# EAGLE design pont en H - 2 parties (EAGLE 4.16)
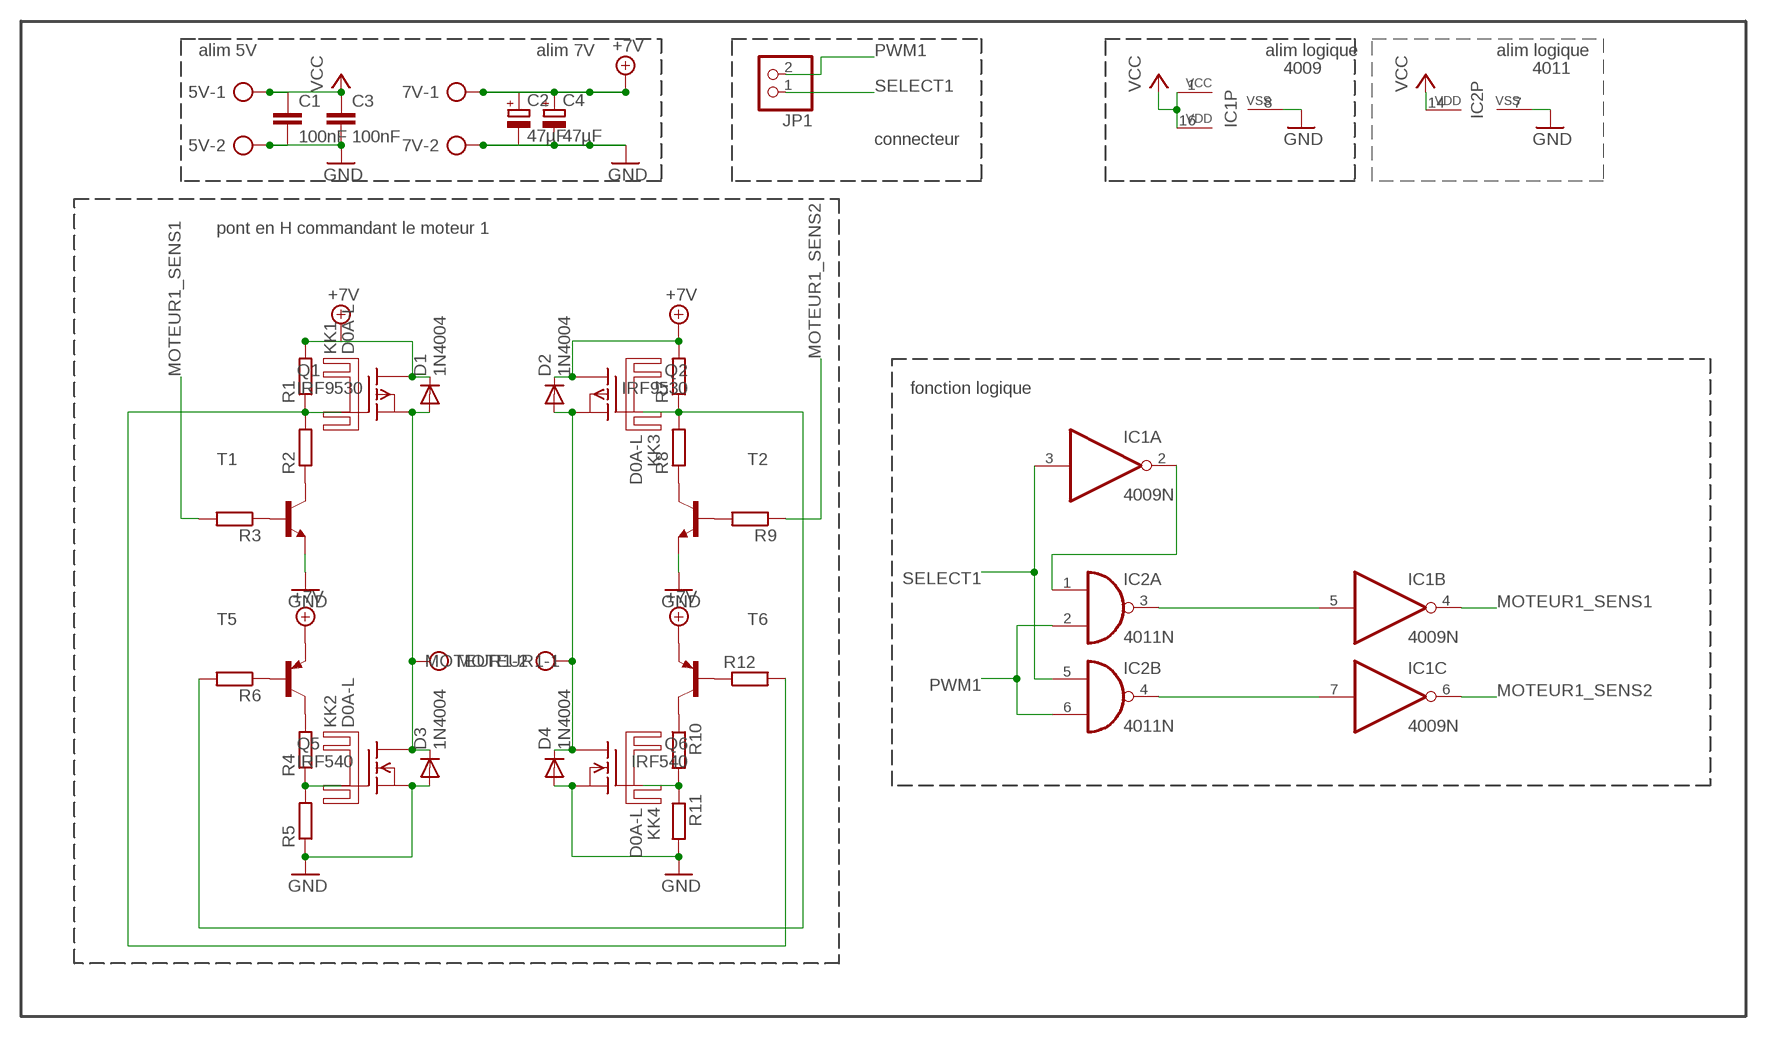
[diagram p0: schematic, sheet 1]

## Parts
5V  AK500/2  [AK500/2]
7V  AK500/2  [AK500/2]
C1  100nF  C-EU025-024X044  [C025-024X044]
C2  47µF  CPOL-EUE2-5  [E2-5]
C3  100nF  C-EU025-024X044  [C025-024X044]
C4  47µF  CPOL-EUE2-5  [E2-5]
D1  1N4004  [DO41-10]
D2  1N4004  [DO41-10]
D3  1N4004  [DO41-10]
D4  1N4004  [DO41-10]
IC1  4009N  [DIL16]
IC2  4011N  [DIL14]
JP1  PINHD-1X2  [1X02]
KK1  D0A-L  [D02A-L]
KK2  D0A-L  [D02A-L]
KK3  D0A-L  [D02A-L]
KK4  D0A-L  [D02A-L]
MOTEUR1  AK500/2  [AK500/2]
Q1  IRF9530  [TO220]
Q2  IRF9530  [TO220]
Q5  IRF540  [TO220]
Q6  IRF540  [TO220]
R1  R-EU_0207/10  [0207/10]
R2  R-EU_0207/10  [0207/10]
R3  R-EU_0207/10  [0207/10]
R4  R-EU_0207/10  [0207/10]
R5  R-EU_0207/10  [0207/10]
R6  R-EU_0207/10  [0207/10]
R7  R-EU_0207/10  [0207/10]
R8  R-EU_0207/10  [0207/10]
R9  R-EU_0207/10  [0207/10]
R10  R-EU_0207/10  [0207/10]
R11  R-EU_0207/10  [0207/10]
R12  R-EU_0207/10  [0207/10]
T1  BC846-NPN-SOT23-BEC  [SOT23-BEC]
T2  BC846-NPN-SOT23-BEC  [SOT23-BEC]
T5  BC858A-PNP-SOT23-BEC  [SOT23-BEC]
T6  BC858A-PNP-SOT23-BEC  [SOT23-BEC]

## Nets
+7V: 7V.1 C2.+ C4.+ D1.C D2.C Q1.2(D) Q2.2(D) R1.2 R7.2 T5.E T6.E
GND: 5V.2 7V.2 C1.2 C2.- C3.2 C4.- D3.A D4.A IC1.8(P:VSS) IC2.7(P:VSS) Q5.3(S) Q6.3(S) R5.1 R11.2 T1.E T2.E
MOTEUR1_SENS1: IC1.4(B:O) R3.2
MOTEUR1_SENS2: IC1.6(C:O) R9.1
N$1: Q1.1(G) R1.1 R2.2 R12.2
N$2: R2.1 T1.C
N$3: R3.1 T1.B
N$4: Q5.1(G) R4.1 R5.2
N$5: R4.2 T5.C
N$6: R6.1 T5.B
N$7: Q2.1(G) R6.2 R7.1 R8.2
N$8: R8.1 T2.C
N$9: R9.2 T2.B
N$10: R10.1 T6.C
N$11: Q6.1(G) R10.2 R11.1
N$12: R12.1 T6.B
N$13: D1.A D3.C MOTEUR1.1 Q1.3(S) Q5.2(D)
N$16: D2.A D4.C MOTEUR1.2 Q2.3(S) Q6.2(D)
N$31: IC1.5(B:I) IC2.3(A:O)
N$32: IC1.7(C:I) IC2.4(B:O)
N$36: IC1.2(A:O) IC2.1(A:I0)
PWM1: IC2.2(A:I1) IC2.6(B:I1) JP1.2
SELECT1: IC1.3(A:I) IC2.5(B:I0) JP1.1
VCC: 5V.1 C1.1 C3.1 IC1.1(P:VCC) IC1.16(P:VDD) IC2.14(P:VDD)
Unconnected: IC1.9(D:I) IC1.10(D:O) IC1.11(E:I) IC1.12(E:O) IC1.14(F:I) IC1.15(F:O) IC2.8(C:I0) IC2.9(C:I1) IC2.10(C:O) IC2.11(D:O) IC2.12(D:I0) IC2.13(D:I1)

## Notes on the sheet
- alim 5V | alim 7V | alim logique | alim logique
- 4009 | 4011
- connecteur
- pont en H commandant le moteur 1
- fonction logique

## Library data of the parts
5V 7V MOTEUR1 = con-ptr500:AK500/2: CONNECTOR
C1 C3 = rcl:C-EU: CAPACITOR, European symbol
C2 C4 = rcl:CPOL-EU: POLARIZED CAPACITOR, European symbol
D1-D4 = diode:1N4004: DIODE
IC1 = 40xx:4009: Hex BUFFER, inverting
IC2 = 40xx:4011: Quad 2-input NAND
JP1 = pinhead:PINHD-1X2: PIN HEADER
KK1-KK4 = heatsink:D0A-L: HEATSINK
Q1 Q2 = transistor-fet:IRF9530: P-Channel Enhancement MOSFET (HEXFET); -100V; -12A; 0,3Ohm
Q5 Q6 = transistor-fet:IRF540: N-Channel Enhancement MOSFET (HEXFET); 100V; 28A; 0,077Ohm
R1-R12 = rcl:R-EU_: RESISTOR, European symbol
T1 T2 = transistor:*-NPN-: NPN Transistror
T5 T6 = transistor:*-PNP-: PNP Transistror

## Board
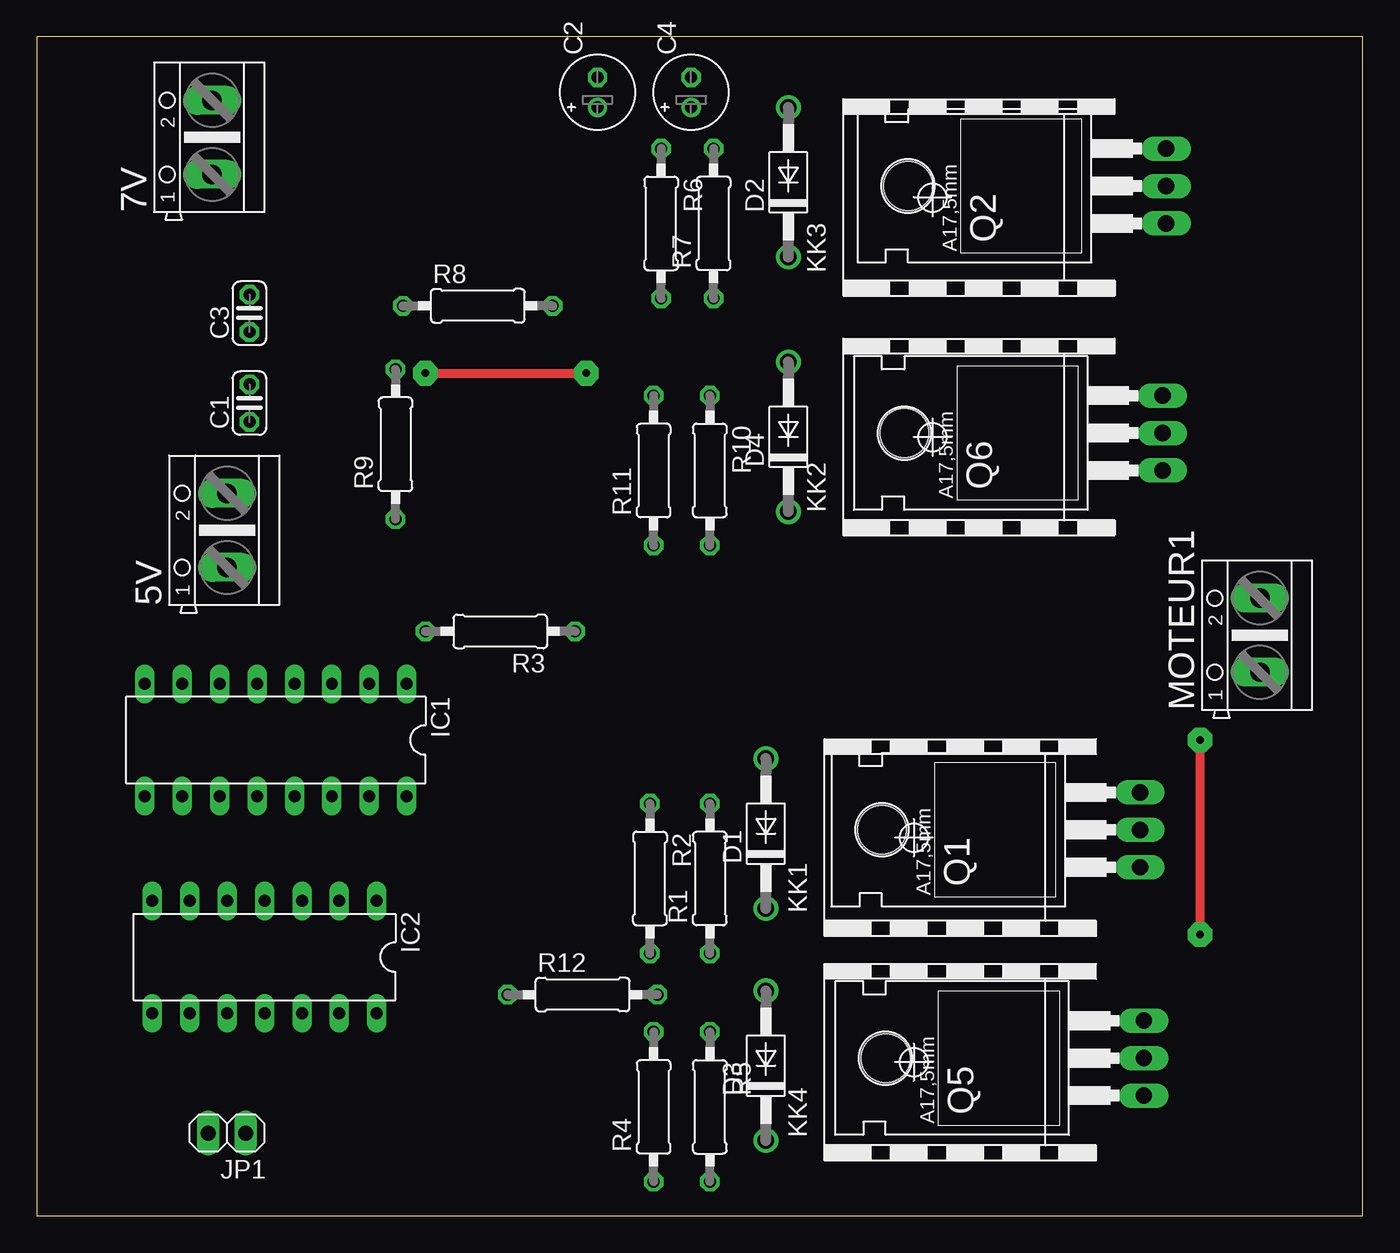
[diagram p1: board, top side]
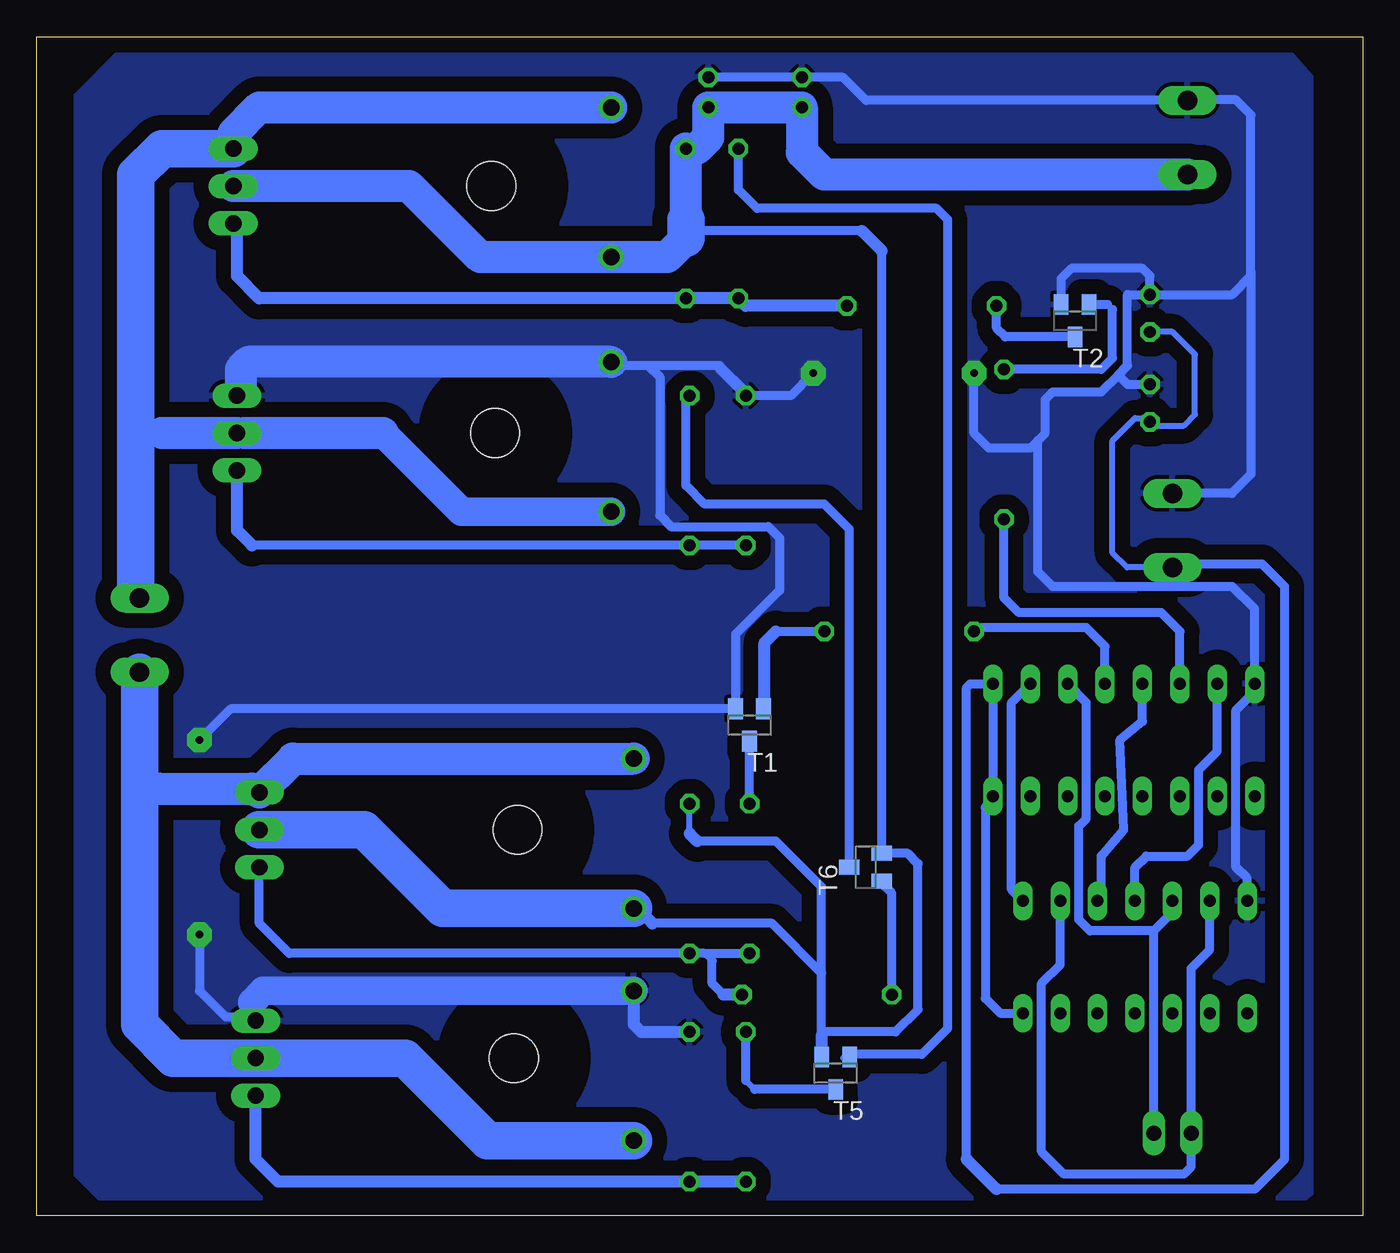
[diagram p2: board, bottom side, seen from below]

Size 90 x 80 mm. Coordinates in mm from the lower left corner, seen from the top.
Outline: 0,0 90,0 90,80 0,80 0,0
Copper layers (1*16): Top 0.035mm / dielectric 1.5mm / Bottom 0.035mm
Design rules "default": minimum track width 10mil, minimum drill 24mil, track to track 8mil, track to pad 8mil, pad to pad 8mil, via to via 8mil, smd to smd 8mil, copper to edge 40mil, drill to drill 8mil, minimum pad ring 10mil, minimum via ring 8mil, stop-mask expansion 4mil, vias tented up to drill 0mil, thermal gap 10mil

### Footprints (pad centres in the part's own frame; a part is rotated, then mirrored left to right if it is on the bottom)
AK500/2 = drill 1.321 long: 1 -2.515,0; 2 2.515,0
C025-024X044 = drill 0.813 octagon: 1 -1.27,0; 2 1.27,0
E2-5 = drill 0.813 pad 1.27 round: + -1.016,0 | drill 0.813 pad 1.27 octagon: - 1.016,0
DO41-10 = drill 1.118 round: A 5.08,0; C -5.08,0
DIL16 = drill 0.813 long: 1 -8.89,-3.81; 2 -6.35,-3.81; 3 -3.81,-3.81; 4 -1.27,-3.81; 5 1.27,-3.81; 6 3.81,-3.81; 7 6.35,-3.81; 8 8.89,-3.81; 9 8.89,3.81; 10 6.35,3.81; 11 3.81,3.81; 12 1.27,3.81; 13 -1.27,3.81; 14 -3.81,3.81; 15 -6.35,3.81; 16 -8.89,3.81
DIL14 = drill 0.813 long: 1 -7.62,-3.81; 2 -5.08,-3.81; 3 -2.54,-3.81; 4 0,-3.81; 5 2.54,-3.81; 6 5.08,-3.81; 7 7.62,-3.81; 8 7.62,3.81; 9 5.08,3.81; 10 2.54,3.81; 11 0,3.81; 12 -2.54,3.81; 13 -5.08,3.81; 14 -7.62,3.81
1X02 = drill 1.016 long: 1 -1.27,0; 2 1.27,0
TO220 = drill 1.118 long: 1 -2.54,-6.35; 2 0,-6.35; 3 2.54,-6.35 | hole 3.302: 0,11.176
0207/10 = drill 0.813 octagon: 1 -5.08,0; 2 5.08,0
SOT23-BEC = smd 1 x 1.4: B -0.95,-1.1; C 0,1.1; E 0.95,-1.1

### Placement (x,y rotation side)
5V  12.92,46.51 90 top
7V  11.9,73.18 90 top
C1  14.44,55.15 90 top
C2  38.06,76.23 90 top
C3  14.44,61.24 90 top
C4  44.41,76.23 90 top
D1  49.49,25.94 90 top
D2  51.02,70.13 90 top
D3  49.49,10.19 90 top
D4  51.02,52.86 90 top
IC1  16.22,32.29 180 top
IC2  15.46,17.55 180 top
JP1  12.92,5.62 180 top
KK1  64.99,25.68 0 top
KK2  66.26,52.86 0 top
KK3  66.26,69.12 0 top
KK4  64.99,10.44 0 top
MOTEUR1  83.02,39.4 90 top
Q1  68.54,26.19 90 top
Q2  70.32,69.88 90 top
Q5  68.8,10.7 90 top
Q6  70.07,53.11 90 top
R1  45.68,22.89 90 top
R2  41.62,22.89 270 top
R3  31.46,39.65 180 top
R4  41.87,7.39 90 top
R5  45.68,7.39 270 top
R6  42.38,67.34 270 top
R7  45.94,67.34 90 top
R8  29.93,61.75 0 top
R9  24.35,52.35 90 top
R10  45.68,50.57 270 top
R11  41.87,50.57 90 top
R12  37.05,15.01 0 top
T1  41.62,33.3 180 bottom
T2  19.52,60.73 180 bottom
T5  35.78,9.68 180 bottom
T6  33.74,23.65 90 bottom

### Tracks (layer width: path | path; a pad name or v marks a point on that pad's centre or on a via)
+7V
  Bottom 0.406: R7.2 46.19,72.42 | 36.73,12.22 36.73,16.47 | 49.24,20.86 D1.C | 45.68,25.94 R1.2
  Bottom 0.61: 36.73,16.47 40.09,19.84 48.22,19.84 | 45.17,25.43 39.84,25.43 36.73,22.31 36.73,12.22 36.79,12.22 36.54,12.47 31.71,12.47 30.19,14 30.19,23.9 30.88,24.6 T6.E 32.64,65.48 | 34,66.83 45.17,66.83 45.94,67.59
  Bottom 0.813: 48.22,19.84 49.24,20.86 | 36.73,12.22 T5.E | 45.17,25.43 45.68,25.94 | 32.64,65.48 34,66.83
  Bottom 2.184: Q2.2 64.73,69.88 59.91,65.05 D2.C 47.21,65.05 45.94,66.32 | 7V.1 36.56,70.66 38.06,72.16 C2.+ C4.+ 44.41,73.18 45.17,72.42 R7.2 45.94,67.59
  Bottom 2.54: D1.C 62.45,20.86 67.78,26.19 Q1.2 | 45.94,67.59 45.94,66.32
GND  (via drill 0.5 pad 1.68)
  Top 0.61: v26.38,57.18 v37.3,57.18 | v78.96,32.29 v78.96,19.08
  Bottom 0.406: C4.- 44.41,77.5 44.16,77.24 | 38.06,76.99 C2.- | D3.A 49.49,15.52 | 51.02,57.69 D4.A | R11.2 41.87,55.91
  Bottom 0.61: 75.4,14.51 75.4,12.98 Q5.3 75.4,13.49 77.18,13.49 78.96,15.27 v78.96,19.08 | 76.16,55.91 Q6.3 | C2.- 44.16,77.24 | 38.06,76.99 37.81,77.24 35.27,77.24 33.72,75.69 7V.2 11.9,75.72 8.6,75.72 7.58,74.7 7.58,64.04 | 41.87,55.91 43.65,57.69 | 48.48,57.69 51.02,57.69 | 14.19,62.51 8.85,62.51 7.58,63.78 7.58,64.04 | T2.E 20.47,63.59 19.77,64.29 14.95,64.29 14.44,63.78 14.44,62.77 14.19,62.51 | 14.19,62.51 C3.2 15.96,62.51 15.96,57.69 16.6,57.05 | IC2.7 7.84,22.89 8.6,23.65 8.6,34.32 7.33,35.59 IC1.8 7.33,41.18 8.85,42.7 21.04,42.7 22.06,43.72 22.06,52.61 21.55,53.11 | 48.48,57.69 47.71,56.92 47.71,47.53 46.95,46.76 40.35,46.76 39.59,46 39.59,42.45 42.57,39.46 T1.E 76.84,34.4 v78.96,32.29 | 43.65,57.69 48.48,57.69 | 43.65,57.69 43.65,57.43 R11.2 38.82,55.65 v37.3,57.18 | v26.38,57.18 26.38,53.11 25.36,52.1 22.57,52.1 21.55,53.11 | 21.55,53.11 21.55,55.4 21.04,55.91 17.74,55.91 16.6,57.05 | C1.2 15.96,56.42 16.6,57.05 | 5V.2 8.88,49.03 7.58,50.32 7.58,64.04
  Bottom 0.813: R5.1 48.98,12.47 49.49,12.98 D3.A
  Bottom 1.93: D3.A 74.64,15.27 75.4,14.51
  Bottom 2.184: D4.A 75.65,57.94 76.16,57.43 76.16,55.91
  pour Bottom (isolate 1.016): 5.3,79.28 84.29,79.02 87.34,75.97 87.34,2.82 85.05,0.54 4.79,0.54 3.52,1.55 3.52,77.24
MOTEUR1_SENS1
  Bottom 0.406: R3.2 26.38,39.4 25.87,39.91
  Bottom 0.61: IC1.4 17.49,38.64 18.76,39.91 25.87,39.91
MOTEUR1_SENS2
  Bottom 0.61: IC1.6 12.41,39.65 13.68,40.92 23.33,40.92 24.35,41.94 R9.1
N$1
  Bottom 0.406: R1.1 44.67,17.81 44.16,17.3
  Bottom 0.61: R2.2 44.67,17.81 72.86,17.81 74.89,19.84 Q1.1 | 43.4,15.01 44.16,15.78 44.16,17.3
  Bottom 0.813: R12.2 43.4,15.01
N$2
  Bottom 0.61: R2.1 T1.C
N$3
  Bottom 0.406: 40.67,34.51 40.6,34.57
  Bottom 0.61: 39.84,39.65 R3.1
  Bottom 0.813: 39.84,39.65 40.6,38.89 40.6,34.57 | T1.B 40.67,34.51
N$4
  Bottom 0.406: R5.2 45.68,2.06 45.43,2.31
  Bottom 0.813: R4.1 45.43,2.31 | R5.2 73.62,2.31 75.15,3.84 Q5.1
N$5
  Bottom 0.406: 41.28,8.58 41.87,9.17
  Bottom 0.61: T5.C 41.28,8.58 | 41.87,9.17 R4.2
N$6
  Bottom 0.406: 35.18,10.78 35.27,10.7 | 35.18,10.78 T5.B | 35.01,10.95 35.18,10.78
  Bottom 0.61: R6.1 42.38,69.62 41.11,68.35 28.92,68.35 28.16,67.59 28.16,12.73 29.93,10.95 35.01,10.95
N$7
  Bottom 0.406: R7.1 45.94,62 45.68,62.26 | 76.92,67.59 Q2.1 76.42,67.08 | 41.87,61.75 R6.2
  Bottom 0.813: R6.2 45.68,62.26 | R7.1 74.89,62.26 76.42,63.78 76.42,67.08 | R8.2 41.87,61.75
N$8
  Bottom 0.61: T2.C 24.26,59.63 24.85,60.23 R8.1
N$9
  Bottom 0.406: 16.98,61.5 17.32,61.83 | R9.2 24.6,57.43
  Bottom 0.61: 17.32,61.83 T2.B | 16.98,61.5 16.98,58.19 17.74,57.43 R9.2
N$10
  Bottom 0.406: 45.94,55.4 R10.1
  Bottom 0.61: T6.C 34.84,46.59 36.54,48.29 44.67,48.29 45.94,49.56 45.94,55.4
N$11
  Bottom 0.406: R10.2 45.94,45.24 | Q6.1 76.67,50.32 76.42,50.07
  Bottom 0.61: R11.1 R10.2 75.4,45.49
  Bottom 0.813: 75.4,45.49 76.42,46.51 76.42,50.07
N$12
  Bottom 0.406: 32.73,22.63 32.66,22.7 T6.B
  Bottom 0.61: R12.1 31.97,21.87 32.73,22.63
N$13
  Bottom 0.61: MOTEUR1.1 83.02,30.25 81.75,28.98 | Q1.3 74.89,28.48 75.4,28.98 | 75.15,10.44 Q5.2 75.4,10.7 75.15,10.44
  Bottom 2.184: 81.75,28.98 75.4,28.98 | D1.A 72.61,31.02 Q1.3
  Bottom 2.54: MOTEUR1.1 83.02,12.98 80.73,10.7 75.4,10.7 64.99,10.7 59.4,5.11 D3.C
N$16
  Bottom 0.61: 83.27,42.45 82.51,41.68 82.77,41.68 83.02,41.94 | 83.02,41.94 83.27,42.19 | 83.02,41.94 MOTEUR1.2 | 81.5,53.11 83.27,51.34 | 76.67,72.16 Q2.3 76.67,73.43 | Q6.2 76.16,52.86 75.91,53.11
  Bottom 1.93: D4.C 61.18,47.78 66.51,53.11
  Bottom 2.184: Q6.2 81.5,53.11 | D2.A 74.89,75.21 76.67,73.43 | 66.51,53.11 75.91,53.11
  Bottom 2.54: Q2.3 81.5,72.42 83.27,70.64 83.27,51.34 83.27,42.45
N$31
  Bottom 0.406: IC2.3 17.74,21.62
  Bottom 0.61: IC1.5 14.95,33.56 16.47,32.29 16.22,26.19 17.74,24.41 17.74,21.62
N$32
  Bottom 0.61: IC1.7 9.87,31.52 11.14,30.25 11.14,25.17 11.9,24.41 14.69,24.41 15.46,23.65 IC2.4
N$36
  Bottom 0.61: IC1.2 23.84,34.83 23.84,22.13 IC2.1
PWM1
  Bottom 0.61: IC2.6 10.38,18.06 11.65,16.79 JP1.2 11.65,3.33 12.15,2.82 20.28,2.82 21.81,4.35 21.81,15.78 20.54,17.05 IC2.2
SELECT1
  Bottom 0.61: IC2.5 12.92,20.6 14.19,19.33 | JP1.1 14.19,19.33 | 14.19,19.33 18.5,19.33 19.27,20.09 19.27,26.44 18.76,26.95 18.76,34.83 IC1.3
VCC
  Bottom 0.406: C3.1 12.92,59.97 11.39,58.45 11.39,54.38 12.15,53.62 14.44,53.62 C1.1 14.69,53.88 14.95,54.13 15.46,54.13 16.98,52.61 16.98,44.99 15.99,43.99 5V.1
  Bottom 0.61: IC2.14 24.6,13.74 25.62,14.76 25.62,27.71 IC1.16 IC1.1 26.63,36.1 26.89,35.84 26.89,3.84 | 24.85,1.81 7.33,1.81 5.3,3.84 5.3,42.7 6.82,44.22 12.92,44.22 13.15,43.99 | 13.15,43.99 13.17,43.97 | 13.15,43.99 5V.1
  Bottom 0.813: 24.85,1.81 26.89,3.84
